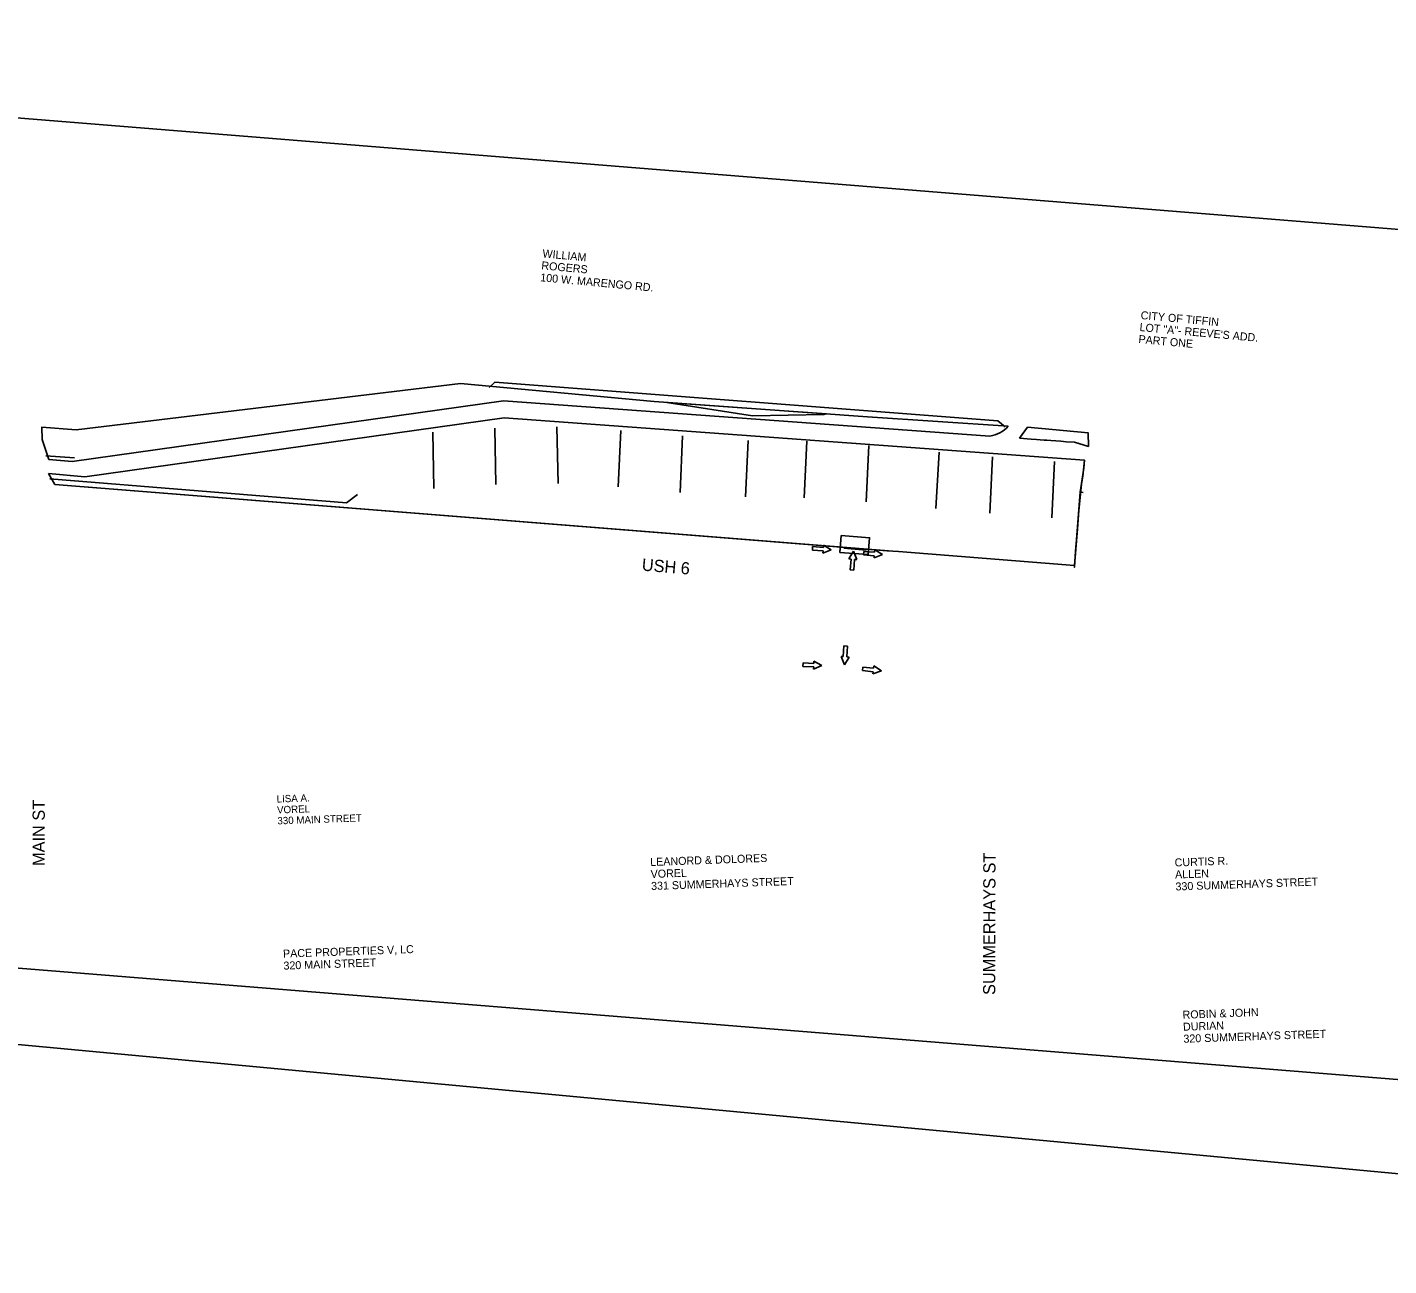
# Model space of a CAD drawing. Extents: x 20499351 to 20505779, y 7953198 to 7954637.
# Drawn here: x 20500945.7 to 20501428, y 7953706.6 to 7954145 of the extents above; entities that cross this region are included whole.
import ezdxf

# ---------------------------------------------------------------- set-up
doc = ezdxf.new("R2010")
doc.units = 0
for name, color, linetype in [('ClearGrub', 7, 'Continuous'), ('Draft_DNC', 7, 'Continuous'), ('dsnCellElements', 7, 'Continuous'), ('ErosionControl', 7, 'Continuous'), ('NamedBoundary', 7, 'Continuous'), ('Seeding', 7, 'Continuous'), ('Text', 7, 'Continuous')]:
    doc.layers.add(name, color=color, linetype=linetype)

msp = doc.modelspace()

# ---------------------------------------------------------------- linework, layer by layer
at = {"layer": 'ClearGrub'}
msp.add_lwpolyline([(20501172.24, 7954012.2), (20501202.6, 7954007.42), (20501227.91, 7954007.89), (20501228.78, 7954008.15), (20501172.24, 7954012.2)], dxfattribs=at)
at = {"layer": 'Draft_DNC'}
msp.add_lwpolyline([(20501791.06, 7953833.84), (20501779.66, 7953706.56), (20499351.13, 7953933.78), (20499411.85, 7954636.65), (20501855.07, 7954405.25), (20501814.1, 7954091.19), (20501791.1, 7953834.34)], dxfattribs=at)
at = {"layer": 'dsnCellElements'}
for p, q in [((20501223.81, 7953959.88), (20501223.89, 7953961.15)), ((20501223.89, 7953961.15), (20501227.7, 7953960.88)), ((20501227.7, 7953960.88), (20501227.76, 7953961.67)), ((20501227.76, 7953961.67), (20501230.51, 7953960.04)), ((20501227.61, 7953959.61), (20501223.81, 7953959.88)), ((20501230.51, 7953960.04), (20501227.56, 7953958.82)), ((20501227.56, 7953958.82), (20501227.61, 7953959.61)), ((20501236.73, 7953956.78), (20501238.37, 7953959.53)), ((20501237.53, 7953956.72), (20501236.73, 7953956.78)), ((20501237.24, 7953952.91), (20501237.53, 7953956.72)), ((20501238.37, 7953959.53), (20501239.59, 7953956.56)), ((20501238.79, 7953956.62), (20501238.51, 7953952.82)), ((20501239.59, 7953956.56), (20501238.79, 7953956.62)), ((20501241.94, 7953958.19), (20501242.03, 7953959.46)), ((20501245.75, 7953957.93), (20501241.94, 7953958.19)), ((20501242.03, 7953959.46), (20501245.84, 7953959.2)), ((20501248.65, 7953958.38), (20501245.7, 7953957.14)), ((20501245.7, 7953957.14), (20501245.75, 7953957.93)), ((20501245.84, 7953959.2), (20501245.89, 7953960)), ((20501245.89, 7953960), (20501248.65, 7953958.38)), ((20501238.51, 7953952.82), (20501237.24, 7953952.91)), ((20501235.22, 7953919.3), (20501233.96, 7953922.25)), ((20501233.96, 7953922.25), (20501234.76, 7953922.2)), ((20501234.76, 7953922.2), (20501234.99, 7953926.01)), ((20501234.99, 7953926.01), (20501236.26, 7953925.93)), ((20501236.82, 7953922.07), (20501235.22, 7953919.3)), ((20501236.26, 7953925.93), (20501236.03, 7953922.12)), ((20501236.03, 7953922.12), (20501236.82, 7953922.07)), ((20501220.46, 7953918.74), (20501220.53, 7953920.02)), ((20501224.27, 7953918.55), (20501220.46, 7953918.74)), ((20501220.53, 7953920.02), (20501224.34, 7953919.83)), ((20501227.17, 7953919.05), (20501224.24, 7953917.76)), ((20501224.24, 7953917.76), (20501224.27, 7953918.55)), ((20501224.34, 7953919.83), (20501224.38, 7953920.62)), ((20501224.38, 7953920.62), (20501227.17, 7953919.05)), ((20501241.55, 7953917.24), (20501241.68, 7953918.51)), ((20501245.35, 7953916.86), (20501241.55, 7953917.24)), ((20501241.68, 7953918.51), (20501245.47, 7953918.13)), ((20501248.26, 7953917.21), (20501245.27, 7953916.07)), ((20501245.27, 7953916.07), (20501245.35, 7953916.86)), ((20501245.47, 7953918.13), (20501245.55, 7953918.92)), ((20501245.55, 7953918.92), (20501248.26, 7953917.21))]:
    msp.add_line(p, q, dxfattribs=at)
at = {"layer": 'ErosionControl'}
for p, q in [((20500966.14, 7953985.84), (20501114.61, 7954006.72)), ((20501133.72, 7953983.54), (20501133.31, 7954003.54)), ((20501089.77, 7953981.72), (20501089.36, 7954001.71)), ((20501111.72, 7953983.15), (20501111.31, 7954003.14)), ((20501155.02, 7953982.31), (20501155.94, 7954002.29)), ((20501176.93, 7953980.34), (20501177.86, 7954000.32)), ((20501200.14, 7953978.79), (20501201.07, 7953998.76)), ((20501220.89, 7953978.47), (20501221.82, 7953998.45)), ((20501242.84, 7953976.98), (20501243.77, 7953996.96)), ((20501267.59, 7953974.66), (20501268.7, 7953994.62)), ((20501286.65, 7953972.97), (20501287.58, 7953992.94)), ((20501308.59, 7953971.32), (20501309.52, 7953991.3)), ((20500955.44, 7953983.15), (20500953.26, 7953987.01)), ((20500953.26, 7953987.01), (20500966.14, 7953985.84)), ((20501252.3, 7953959.56), (20500955.44, 7953983.15)), ((20501319.19, 7953983.27), (20501318.2, 7953973.93)), ((20501318.21, 7953973.97), (20501317.69, 7953967.45)), ((20501318.2, 7953973.95), (20501317.69, 7953967.5)), ((20501318.2, 7953973.93), (20501318.2, 7953973.95)), ((20501242.92, 7953959.93), (20501234.94, 7953960.59)), ((20501317.17, 7953960.97), (20501316.92, 7953957.78)), ((20501316.66, 7953954.52), (20501254.33, 7953959.4))]:
    msp.add_line(p, q, dxfattribs=at)
for points in [[(20501109.29, 7954017.52), (20501111.36, 7954019.4), (20501289.52, 7954005.74), (20501292.08, 7954003.54)], [(20501114.61, 7954006.72), (20501320.18, 7953991.82), (20501320.18, 7953991.82), (20501320.18, 7953991.82), (20501320.18, 7953991.82), (20501319.92, 7953988.91), (20501318.72, 7953980.41), (20501319.19, 7953983.27)], [(20500953.68, 7953985.15), (20501058.78, 7953976.69), (20501062.66, 7953979.64)], [(20501317.69, 7953967.45), (20501317.69, 7953967.43), (20501318.2, 7953973.93), (20501318.2, 7953973.95)], [(20501318.2, 7953973.95), (20501318.2, 7953973.93), (20501318.2, 7953973.93), (20501318.21, 7953973.97)], [(20501317.69, 7953967.5), (20501317.69, 7953967.47), (20501317.17, 7953960.94), (20501317.17, 7953960.97)], [(20501254.33, 7953959.4), (20501254.33, 7953959.4), (20501252.3, 7953959.56), (20501252.3, 7953959.56)], [(20501316.92, 7953957.78), (20501316.61, 7953953.84), (20501316.61, 7953953.84), (20501316.66, 7953954.52)]]:
    msp.add_lwpolyline(points, dxfattribs=at)
msp.add_lwpolyline([(20501234.02, 7953965.07), (20501233.54, 7953959.11), (20501243.62, 7953958.32), (20501244.09, 7953964.27)], close=True, dxfattribs=at)
at = {"layer": 'NamedBoundary'}
msp.add_lwpolyline([(20500712.21, 7954131.46), (20500688.08, 7953832.43), (20501625.52, 7953756.77), (20501649.66, 7954055.8)], close=True, dxfattribs=at)
at = {"layer": 'Seeding'}
for p, q in [((20500961.66, 7953991.27), (20501114.4, 7954012.75)), ((20501114.4, 7954012.75), (20501286.7, 7954000.26)), ((20500966.14, 7953985.84), (20501114.61, 7954006.72)), ((20501297.16, 7953999.6), (20501299.97, 7954003.5)), ((20500951, 7953999.06), (20500953.34, 7953992.03)), ((20501301.27, 7953999.21), (20501297.15, 7953999.51)), ((20500952.3, 7953993.35), (20500962.39, 7953992.58)), ((20500953.34, 7953992.03), (20500961.66, 7953991.27)), ((20500955.44, 7953983.15), (20500953.26, 7953987.01)), ((20500953.26, 7953987.01), (20500966.14, 7953985.84)), ((20501250.28, 7953959.72), (20500955.44, 7953983.15)), ((20501318.72, 7953980.43), (20501317.69, 7953967.43)), ((20501319.7, 7953980.27), (20501318.72, 7953980.42)), ((20501318.72, 7953980.41), (20501319.7, 7953980.27)), ((20501317.69, 7953967.5), (20501316.65, 7953954.44)), ((20501316.65, 7953954.44), (20501254.33, 7953959.4)), ((20501316.65, 7953954.46), (20501316.65, 7953954.44))]:
    msp.add_line(p, q, dxfattribs=at)
for points in [[(20501293.22, 7954003.82), (20501243.35, 7954007.11), (20501167.79, 7954012.52), (20501099.12, 7954018.93), (20500963.05, 7954002.56), (20500950.9, 7954003.48), (20500951, 7953999.06)], [(20501114.61, 7954006.72), (20501320.18, 7953991.82), (20501319.67, 7953986.13), (20501318.72, 7953980.41), (20501318.72, 7953980.41), (20501318.72, 7953980.41), (20501318.72, 7953980.41), (20501318.72, 7953980.41)], [(20501299.97, 7954003.5), (20501321.5, 7954001.45), (20501321.61, 7953996.61), (20501316.65, 7953998.09), (20501313.74, 7953998.3), (20501311.84, 7953998.44), (20501308.33, 7953998.7), (20501306.9, 7953998.8), (20501305.91, 7953998.87), (20501304.53, 7953998.97), (20501303.24, 7953999.07), (20501301.27, 7953999.21)], [(20501316.65, 7953954.44), (20501318.72, 7953980.41), (20501318.72, 7953980.41), (20501316.65, 7953954.44)], [(20501318.72, 7953980.42), (20501318.72, 7953980.41), (20501318.72, 7953980.41), (20501318.72, 7953980.43)], [(20501317.69, 7953967.43), (20501317.69, 7953967.5), (20501317.7, 7953967.58), (20501317.69, 7953967.5)], [(20501254.33, 7953959.4), (20501254.33, 7953959.4), (20501250.28, 7953959.72), (20501250.28, 7953959.72)], [(20501316.65, 7953954.44), (20501316.65, 7953954.43), (20501316.65, 7953954.44), (20501316.65, 7953954.46)]]:
    msp.add_lwpolyline(points, dxfattribs=at)
msp.add_ellipse((20501285.05, 7954011.04), major_axis=(-4.47, 9.94), ratio=0.99878, start_param=2.869997, end_param=3.566681, dxfattribs=at)

# ---------------------------------------------------------------- texts
at = {"layer": 'Text'}
for s, height, rotation, p in [('WILLIAM', 2.835, 354.7645, (20501128.11, 7954063.58)), ('ROGERS', 2.835, 354.7645, (20501127.72, 7954059.35)), ('100 W. MARENGO RD.', 2.8346, 354.7645, (20501127.33, 7954055.11)), ('CITY OF TIFFIN', 2.8346, 354.7645, (20501340.01, 7954041.74)), ('LOT "A"- REEVE\'S ADD.', 2.8346, 354.7645, (20501339.62, 7954037.51)), ('PART ONE', 2.835, 354.7645, (20501339.23, 7954033.27)), ('USH 6', 4.32, 355.0805, (20501163.27, 7953952.69)), ('LISA A. ', 2.58, 2.0248, (20501034.09, 7953870.53)), ('MAIN ST', 4.32, 89.9003, (20500951.89, 7953848.09)), ('VOREL', 2.58, 2.0248, (20501034.22, 7953866.66)), ('330 MAIN STREET', 2.5802, 2.0248, (20501034.36, 7953862.8)), ('LEANORD & DOLORES', 2.8346, 2.0248, (20501166.42, 7953848.08)), ('SUMMERHAYS ST', 4.32, 89.9003, (20501288.6, 7953802.43)), ('CURTIS R.', 2.835, 2.0248, (20501352.18, 7953847.9)), ('VOREL', 2.835, 2.0248, (20501166.57, 7953843.83)), ('ALLEN', 2.835, 2.0248, (20501352.33, 7953843.65)), ('331 SUMMERHAYS STREET', 2.8346, 2.0248, (20501166.72, 7953839.58)), ('330 SUMMERHAYS STREET', 2.8346, 2.0248, (20501352.48, 7953839.4)), ('PACE PROPERTIES V, LC', 2.8346, 2.0248, (20501036.35, 7953815.63)), ('320 MAIN STREET', 2.8346, 2.0248, (20501036.5, 7953811.38)), ('ROBIN & JOHN', 2.8346, 2.0248, (20501354.99, 7953794)), ('DURIAN', 2.835, 2.0248, (20501355.14, 7953789.75)), ('320 SUMMERHAYS STREET', 2.8346, 2.0248, (20501355.29, 7953785.5))]:
    msp.add_text(s, height=height, rotation=rotation, dxfattribs=at).set_placement(p)

doc.saveas('drawing.dxf')
